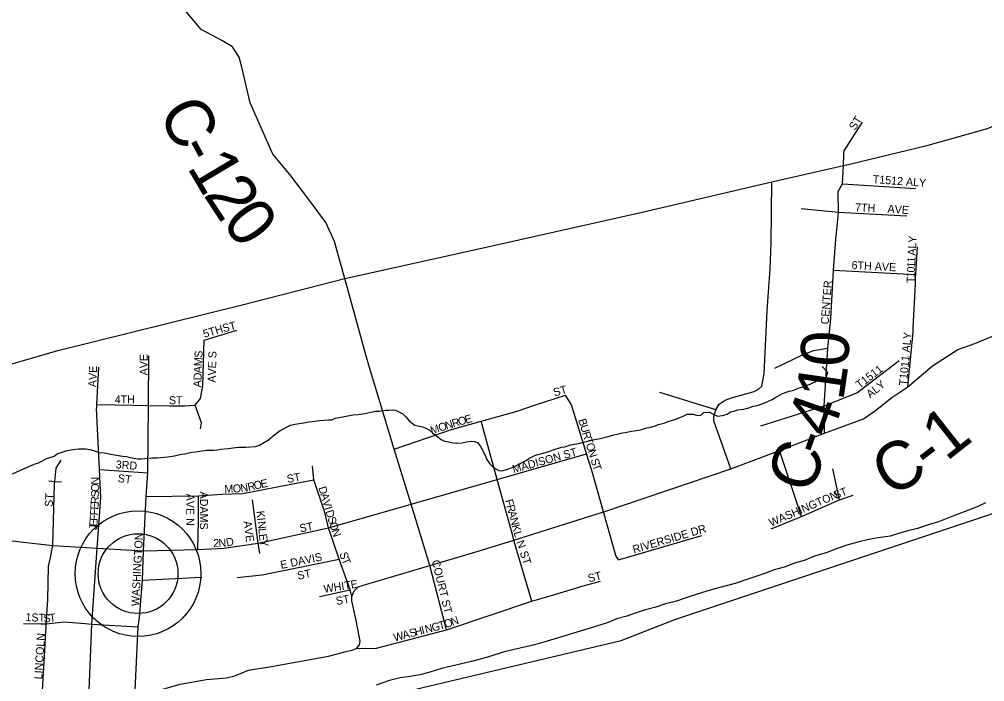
# Model space of a CAD drawing. Extents: x 1949938.81 to 1949945.61, y 152207.65 to 152214.09.
# Drawn here: x 1949943.289 to 1949944.431, y 152208.158 to 152208.942 of the extents above; entities that cross this region are included whole.
import ezdxf

# ---------------------------------------------------------------- set-up
doc = ezdxf.new("R2010")
doc.units = 0
for name, color, linetype in [('GM_X_County', 7, 'Continuous'), ('GM_X_County_Road', 7, 'Continuous'), ('GM_X_County_Road_Text', 7, 'Continuous'), ('GM_X_Major_River', 7, 'Continuous'), ('GM_X_Minor_River', 7, 'Continuous'), ('GM_X_Township', 7, 'Continuous'), ('GM_X_Township_ROW', 7, 'Continuous'), ('GM_X_Township_Subdivision', 7, 'Continuous'), ('GM_X_Township_Subdivision_Text', 7, 'Continuous'), ('GM_X_Unincorporated', 7, 'Continuous'), ('GM_X_Unincorporated_Location', 7, 'Continuous'), ('GM_X_US_Route', 7, 'Continuous')]:
    doc.layers.add(name, color=color, linetype=linetype)

msp = doc.modelspace()

# ---------------------------------------------------------------- linework, layer by layer
at = {"layer": 'GM_X_County'}
msp.add_lwpolyline([(1949942.5103, 152208.0107), (1949942.8268, 152208.0046), (1949942.9926, 152208.0073), (1949943.0418, 152208.019), (1949943.1902, 152208.0433), (1949943.3242, 152208.0581), (1949943.5551, 152208.1009), (1949944.0013, 152208.2067), (1949944.0649, 152208.2317), (1949944.5237, 152208.3846), (1949944.9116, 152208.528), (1949945.0312, 152208.5697), (1949945.2633, 152208.6645), (1949945.3744, 152208.725), (1949945.418, 152208.7524), (1949945.4377, 152208.7581), (1949945.4771, 152208.7673), (1949945.504, 152208.7825), (1949945.5586, 152208.8115), (1949945.5958, 152208.8237), (1949945.6069, 152208.8266)], dxfattribs=at)
at = {"layer": 'GM_X_County_Road'}
for points in [[(1949943.6692, 152208.6533), (1949943.6622, 152208.679), (1949943.6518, 152208.7014), (1949943.6305, 152208.7301), (1949943.6093, 152208.7583), (1949943.5891, 152208.7822), (1949943.5622, 152208.843), (1949943.5524, 152208.8851), (1949943.5493, 152208.8969), (1949943.5414, 152208.9094), (1949943.5289, 152208.9166), (1949943.5175, 152208.9227), (1949943.5043, 152208.9299), (1949943.4471, 152208.9983), (1949943.4285, 152209.0254), (1949943.4187, 152209.0361), (1949943.4074, 152209.0495), (1949943.4025, 152209.0598), (1949943.3956, 152209.0803), (1949943.3888, 152209.1174), (1949943.3776, 152209.1483), (1949943.3761, 152209.156)], [(1949944.1312, 152208.4101), (1949944.1108, 152208.4668), (1949944.1111, 152208.472), (1949944.1132, 152208.4796), (1949944.1173, 152208.4865), (1949944.1242, 152208.491), (1949944.1319, 152208.4938), (1949944.1585, 152208.5015), (1949944.1636, 152208.5041), (1949944.1677, 152208.5079), (1949944.1706, 152208.5222), (1949944.174, 152208.597), (1949944.1775, 152208.6464), (1949944.1789, 152208.6773), (1949944.1795, 152208.7497)], [(1949943.6993, 152208.5449), (1949943.6742, 152208.6353), (1949943.6692, 152208.6533)], [(1949943.6911, 152208.2011), (1949943.6916, 152208.2018), (1949943.6924, 152208.206), (1949943.6911, 152208.2119), (1949943.6877, 152208.2305), (1949943.6825, 152208.2537), (1949943.6825, 152208.2587), (1949943.6852, 152208.2656), (1949943.6901, 152208.2701), (1949943.7005, 152208.2735), (1949943.7749, 152208.2955), (1949943.8321, 152208.3124), (1949943.8743, 152208.3254), (1949943.9805, 152208.3589), (1949943.9809, 152208.359), (1949944.1312, 152208.4101), (1949944.1886, 152208.4316), (1949944.2419, 152208.4522), (1949944.2881, 152208.4691), (1949944.3024, 152208.4788), (1949944.3216, 152208.4942), (1949944.3406, 152208.507), (1949944.3696, 152208.5317), (1949944.3995, 152208.5511), (1949944.4199, 152208.5583), (1949944.4487, 152208.5701)], [(1949943.7749, 152208.2955), (1949943.7526, 152208.368), (1949943.7325, 152208.433), (1949943.7099, 152208.5088), (1949943.7036, 152208.5297), (1949943.6993, 152208.5449)], [(1949943.2833, 152208.1115), (1949943.3015, 152208.1115), (1949943.3146, 152208.1145), (1949943.3709, 152208.128), (1949943.4256, 152208.1398), (1949943.4795, 152208.155), (1949943.5105, 152208.1607), (1949943.5341, 152208.1628), (1949943.5442, 152208.1648), (1949943.5604, 152208.1715), (1949943.5851, 152208.1756), (1949943.6548, 152208.1883), (1949943.6743, 152208.1933), (1949943.684, 152208.1959), (1949943.6884, 152208.1978), (1949943.6911, 152208.2011)]]:
    msp.add_lwpolyline(points, dxfattribs=at)
at = {"layer": 'GM_X_Major_River'}
msp.add_lwpolyline([(1949944.4324, 152208.3698), (1949944.4226, 152208.3649), (1949944.4071, 152208.3592), (1949944.3927, 152208.3535), (1949944.3768, 152208.3471), (1949944.3663, 152208.3441), (1949944.3519, 152208.3395), (1949944.3405, 152208.3365), (1949944.3307, 152208.3338), (1949944.3194, 152208.3304), (1949944.3054, 152208.3282), (1949944.2944, 152208.3263), (1949944.2815, 152208.3232), (1949944.2683, 152208.3195), (1949944.2558, 152208.3153), (1949944.2452, 152208.3111), (1949944.2301, 152208.3066), (1949944.218, 152208.3013), (1949944.2074, 152208.2986), (1949944.1942, 152208.2937), (1949944.1825, 152208.2903), (1949944.1722, 152208.2865), (1949944.1617, 152208.2831), (1949944.1511, 152208.2793), (1949944.1363, 152208.2744), (1949944.1257, 152208.2713), (1949944.1121, 152208.2679), (1949944.0977, 152208.2634), (1949944.0815, 152208.2585), (1949944.0667, 152208.2535), (1949944.0539, 152208.2501), (1949944.0422, 152208.2463), (1949944.0285, 152208.2425), (1949944.0179, 152208.2391), (1949944.0081, 152208.2357), (1949943.9956, 152208.2323), (1949943.9858, 152208.2281), (1949943.9748, 152208.2244), (1949943.962, 152208.2206), (1949943.9476, 152208.2164), (1949943.9347, 152208.2122), (1949943.9215, 152208.2085), (1949943.9098, 152208.205), (1949943.8988, 152208.2016), (1949943.8886, 152208.1994), (1949943.8746, 152208.1963), (1949943.8618, 152208.1929), (1949943.8481, 152208.1888), (1949943.8376, 152208.1853), (1949943.8243, 152208.1819), (1949943.8122, 152208.1793), (1949943.8005, 152208.1766), (1949943.7888, 152208.1736), (1949943.7736, 152208.1691), (1949943.7631, 152208.166), (1949943.7517, 152208.1641), (1949943.7396, 152208.1626), (1949943.7271, 152208.1596), (1949943.7112, 152208.1539)], dxfattribs=at)
at = {"layer": 'GM_X_Minor_River'}
for points in [[(1949943.8345, 152208.437), (1949943.8367, 152208.4328), (1949943.8404, 152208.4259), (1949943.8422, 152208.4209), (1949943.8455, 152208.4163), (1949943.8496, 152208.4124), (1949943.853, 152208.4101), (1949943.8567, 152208.4081), (1949943.8601, 152208.4077), (1949943.867, 152208.4095), (1949943.875, 152208.4128), (1949943.8819, 152208.4161), (1949943.888, 152208.4194), (1949943.8922, 152208.422), (1949943.8991, 152208.4256), (1949943.9025, 152208.4267), (1949943.9075, 152208.4282), (1949943.9117, 152208.4292), (1949943.9155, 152208.4303), (1949943.9208, 152208.4325), (1949943.9307, 152208.4354), (1949943.9345, 152208.4361), (1949943.9414, 152208.4382), (1949943.9509, 152208.44), (1949943.9581, 152208.4417), (1949943.9665, 152208.4439), (1949943.9699, 152208.4446), (1949943.9763, 152208.446), (1949943.9843, 152208.4477), (1949943.9931, 152208.4502), (1949943.9965, 152208.4509), (1949944.003, 152208.4524), (1949944.0064, 152208.4531), (1949944.0132, 152208.4545), (1949944.0166, 152208.4548), (1949944.0242, 152208.4562), (1949944.0311, 152208.4583), (1949944.0345, 152208.459), (1949944.0417, 152208.4608), (1949944.0452, 152208.4623), (1949944.052, 152208.464), (1949944.0558, 152208.4655), (1949944.0619, 152208.4677), (1949944.0661, 152208.4687), (1949944.0745, 152208.4724), (1949944.0795, 152208.4746), (1949944.0859, 152208.4745), (1949944.0905, 152208.4736), (1949944.095, 152208.4732), (1949944.0985, 152208.4765), (1949944.1057, 152208.4768), (1949944.1102, 152208.4748), (1949944.1154, 152208.4721), (1949944.1211, 152208.4731), (1949944.1268, 152208.4745), (1949944.1307, 152208.4775), (1949944.1345, 152208.4782), (1949944.1394, 152208.4796), (1949944.1463, 152208.4807), (1949944.1523, 152208.4821), (1949944.1573, 152208.4839), (1949944.1626, 152208.4849), (1949944.1699, 152208.4875), (1949944.1748, 152208.4897), (1949944.1798, 152208.4919), (1949944.184, 152208.4944), (1949944.192, 152208.4989), (1949944.2, 152208.5018), (1949944.2054, 152208.5032), (1949944.2107, 152208.5054), (1949944.2164, 152208.5068), (1949944.2202, 152208.5086), (1949944.2248, 152208.5101), (1949944.2298, 152208.5123), (1949944.2344, 152208.5152), (1949944.2405, 152208.517), (1949944.2439, 152208.5185), (1949944.2459, 152208.5238), (1949944.2392, 152208.5311)], [(1949943.2809, 152208.4039), (1949943.2905, 152208.4083), (1949943.2951, 152208.4105), (1949943.3065, 152208.4153), (1949943.3118, 152208.4171), (1949943.3218, 152208.4222), (1949943.3305, 152208.4251), (1949943.334, 152208.4277), (1949943.3458, 152208.4317), (1949943.3504, 152208.4324), (1949943.3557, 152208.433), (1949943.3595, 152208.4334), (1949943.3636, 152208.4337), (1949943.3678, 152208.4336), (1949943.3727, 152208.4328), (1949943.3769, 152208.4315), (1949943.3833, 152208.4292), (1949943.3897, 152208.4287), (1949943.3972, 152208.4274), (1949943.4018, 152208.4266), (1949943.4112, 152208.4249), (1949943.4158, 152208.4244), (1949943.4222, 152208.4228), (1949943.4293, 152208.4219), (1949943.4331, 152208.4219), (1949943.446, 152208.4228), (1949943.4517, 152208.4231), (1949943.4608, 152208.4237), (1949943.465, 152208.424), (1949943.4726, 152208.4254), (1949943.4806, 152208.4271), (1949943.4851, 152208.4278), (1949943.4931, 152208.4296), (1949943.4977, 152208.4302), (1949943.5056, 152208.4312), (1949943.5106, 152208.4319), (1949943.5193, 152208.4321), (1949943.5238, 152208.4324), (1949943.5273, 152208.4331), (1949943.5364, 152208.4341), (1949943.5417, 152208.4348), (1949943.5489, 152208.4354), (1949943.5538, 152208.4357), (1949943.5572, 152208.4357), (1949943.5686, 152208.4362), (1949943.5724, 152208.4377), (1949943.5774, 152208.4403), (1949943.5839, 152208.4443), (1949943.5893, 152208.4488), (1949943.5931, 152208.4518), (1949943.5977, 152208.4551), (1949943.61, 152208.4614), (1949943.6157, 152208.4628), (1949943.6252, 152208.4645), (1949943.632, 152208.4655), (1949943.6362, 152208.4658), (1949943.6442, 152208.4672), (1949943.6548, 152208.4678), (1949943.6589, 152208.4681), (1949943.6628, 152208.4699), (1949943.67, 152208.471), (1949943.6799, 152208.4731), (1949943.6837, 152208.4738), (1949943.6901, 152208.4744), (1949943.6981, 152208.4754), (1949943.7015, 152208.4761), (1949943.7106, 152208.4782), (1949943.7152, 152208.4782), (1949943.7194, 152208.4788), (1949943.7228, 152208.4792), (1949943.7262, 152208.4795), (1949943.7307, 152208.4798), (1949943.7341, 152208.4794), (1949943.7375, 152208.4778), (1949943.7428, 152208.475), (1949943.7465, 152208.4715), (1949943.7506, 152208.4662), (1949943.7573, 152208.4615), (1949943.7622, 152208.4603), (1949943.766, 152208.4598), (1949943.7701, 152208.4582), (1949943.7739, 152208.4559), (1949943.778, 152208.4524), (1949943.7843, 152208.4477), (1949943.7884, 152208.4446), (1949943.7922, 152208.4427), (1949943.7971, 152208.4418), (1949943.8024, 152208.4406), (1949943.8062, 152208.4401), (1949943.813, 152208.4408), (1949943.8183, 152208.4418), (1949943.8244, 152208.4425), (1949943.8278, 152208.4424), (1949943.8312, 152208.4409), (1949943.8345, 152208.437)]]:
    msp.add_lwpolyline(points, dxfattribs=at)
at = {"layer": 'GM_X_Township'}
msp.add_lwpolyline([(1949942.5103, 152208.0107), (1949942.8268, 152208.0046), (1949942.9926, 152208.0073), (1949943.0418, 152208.019), (1949943.1902, 152208.0433), (1949943.3242, 152208.0581), (1949943.5551, 152208.1009), (1949944.0013, 152208.2067), (1949944.0649, 152208.2317), (1949944.5237, 152208.3846), (1949944.9116, 152208.528), (1949945.0312, 152208.5697), (1949945.2633, 152208.6645), (1949945.3744, 152208.725), (1949945.418, 152208.7524), (1949945.4377, 152208.7581), (1949945.4771, 152208.7673), (1949945.504, 152208.7825), (1949945.5586, 152208.8115), (1949945.5958, 152208.8237), (1949945.6069, 152208.8266)], dxfattribs=at)
at = {"layer": 'GM_X_Township_ROW'}
for points in [[(1949944.3468, 152208.5766), (1949944.3494, 152208.6289)], [(1949944.1132, 152208.4796), (1949944.0469, 152208.5002)]]:
    msp.add_lwpolyline(points, dxfattribs=at)
at = {"layer": 'GM_X_Township_Subdivision'}
for points in [[(1949944.2648, 152208.7825), (1949944.265, 152208.7861), (1949944.2868, 152208.8202)], [(1949944.2579, 152208.7091), (1949944.2583, 152208.7135), (1949944.2579, 152208.7381), (1949944.2631, 152208.7473), (1949944.2642, 152208.7689), (1949944.2648, 152208.7825)], [(1949944.2631, 152208.7473), (1949944.3494, 152208.7417)], [(1949944.2142, 152208.7179), (1949944.2583, 152208.7135), (1949944.3392, 152208.7094)], [(1949944.2419, 152208.4522), (1949944.2414, 152208.4844), (1949944.246, 152208.5529), (1949944.2493, 152208.5878), (1949944.2525, 152208.6449), (1949944.2554, 152208.6812), (1949944.2579, 152208.7091)], [(1949944.3494, 152208.6289), (1949944.3497, 152208.636), (1949944.3499, 152208.6398), (1949944.3518, 152208.6725)], [(1949944.2525, 152208.6449), (1949944.3499, 152208.6398)], [(1949944.3406, 152208.507), (1949944.3466, 152208.5718), (1949944.3468, 152208.5766)], [(1949943.508, 152208.5621), (1949943.5466, 152208.5742)], [(1949943.5034, 152208.4573), (1949943.5046, 152208.4642), (1949943.497, 152208.4854), (1949943.5034, 152208.493), (1949943.5061, 152208.5082), (1949943.508, 152208.5621)], [(1949943.4256, 152208.1398), (1949943.4296, 152208.2228), (1949943.4313, 152208.2339), (1949943.4347, 152208.2781), (1949943.4362, 152208.3128), (1949943.4391, 152208.3771), (1949943.4413, 152208.4052), (1949943.442, 152208.485), (1949943.4425, 152208.5435)], [(1949944.1831, 152208.5292), (1949944.2166, 152208.5453), (1949944.2291, 152208.55), (1949944.246, 152208.5529)], [(1949944.2414, 152208.4844), (1949944.2803, 152208.4999), (1949944.3303, 152208.538)], [(1949943.3807, 152208.4824), (1949943.3808, 152208.4859), (1949943.383, 152208.5303)], [(1949943.8988, 152208.4851), (1949943.9355, 152208.4972)], [(1949943.9586, 152208.4331), (1949943.9424, 152208.4856), (1949943.9355, 152208.4972)], [(1949943.3808, 152208.4859), (1949943.4244, 152208.4852)], [(1949943.4244, 152208.4852), (1949943.4245, 152208.4852), (1949943.442, 152208.485), (1949943.468, 152208.4846)], [(1949943.468, 152208.4846), (1949943.4681, 152208.4846), (1949943.4849, 152208.4843), (1949943.4906, 152208.4847), (1949943.497, 152208.4854)], [(1949943.3709, 152208.128), (1949943.375, 152208.2262), (1949943.3813, 152208.3159), (1949943.3856, 152208.3762), (1949943.3841, 152208.409), (1949943.3806, 152208.4818), (1949943.3807, 152208.4824)], [(1949943.7325, 152208.433), (1949943.8005, 152208.4565), (1949943.8355, 152208.4664), (1949943.8783, 152208.4783), (1949943.8988, 152208.4851)], [(1949944.1667, 152208.4608), (1949944.2414, 152208.4844)], [(1949943.8729, 152208.3307), (1949943.8547, 152208.3972), (1949943.8355, 152208.4664)], [(1949943.9981, 152208.3024), (1949943.9949, 152208.3073), (1949943.9805, 152208.3589), (1949943.9667, 152208.4078), (1949943.9603, 152208.4275), (1949943.9586, 152208.4331)], [(1949944.2148, 152208.3537), (1949944.1886, 152208.4316)], [(1949943.3309, 152208.3923), (1949943.331, 152208.3951), (1949943.3325, 152208.4108), (1949943.3387, 152208.4202)], [(1949943.655, 152208.34), (1949943.7526, 152208.368), (1949943.8547, 152208.3972), (1949943.9603, 152208.4275)], [(1949943.3841, 152208.409), (1949943.4413, 152208.4052)], [(1949943.6497, 152208.3615), (1949943.6496, 152208.362), (1949943.6375, 152208.3971), (1949943.6362, 152208.4134)], [(1949944.2595, 152208.3734), (1949944.2517, 152208.4099)], [(1949943.324, 152208.3956), (1949943.331, 152208.3951), (1949943.3391, 152208.3945)], [(1949943.5982, 152208.3895), (1949943.6375, 152208.3971)], [(1949943.3255, 152208.3031), (1949943.3289, 152208.3194), (1949943.3309, 152208.3923)], [(1949943.4391, 152208.3771), (1949943.5011, 152208.378), (1949943.5288, 152208.3799), (1949943.5533, 152208.3808), (1949943.5741, 152208.3848), (1949943.5982, 152208.3895)], [(1949943.5003, 152208.3144), (1949943.5011, 152208.3481), (1949943.5011, 152208.378)], [(1949943.5735, 152208.3096), (1949943.5719, 152208.322), (1949943.565, 152208.3732)], [(1949944.1786, 152208.3389), (1949944.2148, 152208.3537), (1949944.2595, 152208.3734), (1949944.2759, 152208.3786)], [(1949943.6825, 152208.2587), (1949943.6807, 152208.2667), (1949943.6674, 152208.3031), (1949943.655, 152208.34), (1949943.6497, 152208.3615)], [(1949943.0391, 152208.3366), (1949943.1443, 152208.3303), (1949943.1655, 152208.3289), (1949943.1884, 152208.326), (1949943.2008, 152208.3233), (1949943.2213, 152208.3217), (1949943.2503, 152208.322), (1949943.2669, 152208.323), (1949943.2816, 152208.3246), (1949943.294, 152208.3232), (1949943.3289, 152208.3194)], [(1949943.3289, 152208.3194), (1949943.3813, 152208.3159), (1949943.3817, 152208.3159), (1949943.4362, 152208.3128), (1949943.5003, 152208.3144), (1949943.531, 152208.3159), (1949943.5719, 152208.322), (1949943.655, 152208.34)], [(1949943.8954, 152208.2534), (1949943.8765, 152208.3171), (1949943.8743, 152208.3254), (1949943.8729, 152208.3307)], [(1949943.9981, 152208.3024), (1949944.0968, 152208.3312)], [(1949943.3209, 152208.2238), (1949943.321, 152208.2265), (1949943.3227, 152208.2549), (1949943.3237, 152208.2946), (1949943.3255, 152208.3031)], [(1949943.547, 152208.2814), (1949943.5765, 152208.2844), (1949943.6674, 152208.3031)], [(1949943.7945, 152208.2195), (1949943.7749, 152208.2955)], [(1949943.4347, 152208.2781), (1949943.5051, 152208.2818)], [(1949943.9211, 152208.261), (1949943.949, 152208.2692)], [(1949943.949, 152208.2692), (1949943.9535, 152208.2705), (1949943.977, 152208.277)], [(1949943.6444, 152208.259), (1949943.6807, 152208.2667)], [(1949943.6884, 152208.1978), (1949943.7101, 152208.1975), (1949943.7945, 152208.2195), (1949943.8954, 152208.2534), (1949943.9211, 152208.261)], [(1949943.2941, 152208.2269), (1949943.315, 152208.2265)], [(1949943.3146, 152208.1145), (1949943.319, 152208.1884), (1949943.3209, 152208.2238)], [(1949943.315, 152208.2265), (1949943.3166, 152208.2265), (1949943.321, 152208.2265), (1949943.3423, 152208.2289), (1949943.367, 152208.2268)], [(1949943.367, 152208.2268), (1949943.375, 152208.2262), (1949943.4296, 152208.2228)]]:
    msp.add_lwpolyline(points, dxfattribs=at)
at = {"layer": 'GM_X_Unincorporated'}
for radius in [0.0744, 0.0472]:
    msp.add_circle((1949943.4296, 152208.2859), radius, dxfattribs=at)
at = {"layer": 'GM_X_Unincorporated_Location'}
msp.add_line((1949943.4296, 152208.2859), (1949943.4296, 152208.2859), dxfattribs=at)
at = {"layer": 'GM_X_US_Route'}
msp.add_lwpolyline([(1949942.7677, 152208.3764), (1949942.87, 152208.4095), (1949943.1879, 152208.5073), (1949943.3347, 152208.5501), (1949943.5527, 152208.6039), (1949943.6742, 152208.6353), (1949943.838, 152208.6715), (1949944.0262, 152208.7138), (1949944.1795, 152208.7497), (1949944.2642, 152208.7689), (1949944.2681, 152208.7698), (1949944.3644, 152208.7931), (1949944.4346, 152208.8128), (1949944.628, 152208.8938), (1949944.7057, 152208.9311)], dxfattribs=at)

# ---------------------------------------------------------------- texts
at = {"layer": 'GM_X_County_Road_Text'}
for s, rotation, p in [('C', 297.4718, (1949943.4526, 152208.8317)), ('-', 298.4085, (1949943.4746, 152208.7894)), ('1', 300.6802, (1949943.4869, 152208.7668)), ('2', 303.2559, (1949943.5063, 152208.7343)), ('0', 306.8623, (1949943.5277, 152208.7018)), ('0', 86.7269, (1949944.2696, 152208.5295)), ('1', 81.6999, (1949944.264, 152208.4894)), ('4', 70.8715, (1949944.2498, 152208.445)), ('1', 38.261, (1949944.3861, 152208.418)), ('-', 70.1263, (1949944.2416, 152208.4223)), ('C', 69.9539, (1949944.2255, 152208.3783)), ('C', 29.5236, (1949944.3192, 152208.3755)), ('-', 37.6716, (1949944.3671, 152208.4034))]:
    msp.add_text(s, height=0.0568, rotation=rotation, dxfattribs=at).set_placement(p)
at = {"layer": 'GM_X_Township_Subdivision_Text'}
for s, rotation, p in [('ST', 57.2679, (1949944.278, 152208.8098)), ('T1512 ALY', 355.7947, (1949944.2987, 152208.7481)), ('7TH', 357.7094, (1949944.2779, 152208.7147)), ('AVE', 355.9142, (1949944.3162, 152208.7131)), ('Y', 86.9386, (1949944.3505, 152208.677)), ('A', 86.9167, (1949944.3497, 152208.662)), ('L', 86.9482, (1949944.3502, 152208.6703)), ('1', 86.9386, (1949944.3493, 152208.6537)), ('6TH AVE', 356.9871, (1949944.2737, 152208.6464)), ('0', 87.2512, (1949944.3487, 152208.642)), ('1', 86.9386, (1949944.349, 152208.6478)), ('T', 89.8907, (1949944.3485, 152208.6296)), ('1', 88.5636, (1949944.3485, 152208.6362)), ('CENTER', 85.7619, (1949944.2468, 152208.5806)), ('5TH', 16.9259, (1949943.5081, 152208.5647)), ('ST', 14.0342, (1949943.5307, 152208.5714)), ('T1011 ALY', 84.9571, (1949944.3394, 152208.5081)), ('AVE', 90, (1949943.441, 152208.5205)), ('S', 87.7079, (1949943.5057, 152208.5412)), ('AVE S', 88.5687, (1949943.5215, 152208.5118)), ('AVE', 88.0261, (1949943.3802, 152208.5064)), ('A', 87.7206, (1949943.5049, 152208.5229)), ('M', 87.7044, (1949943.5053, 152208.5312)), ('T1511', 37.1853, (1949944.2834, 152208.5044)), ('D', 87.7263, (1949943.5046, 152208.5145)), ('A', 88.1637, (1949943.5043, 152208.5062)), ('ST', 14.9318, (1949943.9223, 152208.4955)), ('ALY', 38.0485, (1949944.2959, 152208.4932)), ('4TH', 0, (1949943.402, 152208.4873)), ('ST', 0, (1949943.4661, 152208.4864)), ('E', 16.1989, (1949943.8177, 152208.4632)), ('M', 18.4074, (1949943.7772, 152208.4505)), ('O', 18.4085, (1949943.7867, 152208.4537)), ('N', 17.6207, (1949943.7946, 152208.4563)), ('R', 16.3071, (1949943.8025, 152208.4588)), ('O', 16.1846, (1949943.8097, 152208.4609)), ('B', 287.3098, (1949943.9503, 152208.4677)), ('U', 287.3109, (1949943.9526, 152208.4605)), ('R', 287.2858, (1949943.955, 152208.4525)), ('T', 287.3319, (1949943.9573, 152208.4454)), ('O', 287.3094, (1949943.9593, 152208.439)), ('MADISON ST', 15.6687, (1949943.874, 152208.4047)), ('N', 287.2881, (1949943.9617, 152208.4311)), ('3RD', 355.6015, (1949943.4029, 152208.4106)), ('S', 287.3104, (1949943.965, 152208.4207)), ('T', 289.1392, (1949943.967, 152208.414)), ('ST', 10.618, (1949943.6066, 152208.3931)), ('N', 89.9956, (1949943.3835, 152208.3912)), ('ST', 352.8746, (1949943.4052, 152208.3944)), ('R', 12.158, (1949943.5602, 152208.3837)), ('O', 12.1988, (1949943.5675, 152208.3853)), ('E', 12.1956, (1949943.5757, 152208.3871)), ('S', 89.115, (1949943.3834, 152208.376)), ('O', 89.9519, (1949943.3835, 152208.3828)), ('ADAMS', 270, (1949943.5029, 152208.383)), ('M', 2.3344, (1949943.5319, 152208.3814)), ('O', 2.4915, (1949943.5419, 152208.3818)), ('N', 9.0396, (1949943.5514, 152208.3823)), ('D', 286.6247, (1949943.6428, 152208.3876)), ('WASHINGTON', 23.2784, (1949944.1787, 152208.3413)), ('ST', 20.556, (1949944.2546, 152208.3738)), ('ST', 86.4256, (1949943.3285, 152208.3647)), ('R', 86.8391, (1949943.383, 152208.3681)), ('AVE N', 270, (1949943.4866, 152208.3805)), ('A', 286.6245, (1949943.6452, 152208.3797)), ('V', 286.6245, (1949943.6476, 152208.3717)), ('F', 285.0339, (1949943.8637, 152208.3726)), ('F', 86.3638, (1949943.3821, 152208.3547)), ('E', 86.3614, (1949943.3825, 152208.3614)), ('K', 276.3734, (1949943.5696, 152208.3598)), ('I', 286.6243, (1949943.65, 152208.3637)), ('D', 286.6245, (1949943.6512, 152208.3597)), ('R', 285.0098, (1949943.8654, 152208.3662)), ('E', 86.3639, (1949943.3813, 152208.3414)), ('F', 86.3804, (1949943.3817, 152208.3481)), ('I', 276.3517, (1949943.5705, 152208.3516)), ('S', 286.6242, (1949943.6536, 152208.3517)), ('A', 285.0241, (1949943.8673, 152208.3589)), ('N', 285.0342, (1949943.8695, 152208.3509)), ('J', 86.3694, (1949943.381, 152208.3373)), ('AVE', 277.8491, (1949943.5543, 152208.3477)), ('N', 276.3863, (1949943.5709, 152208.3474)), ('L', 276.3515, (1949943.5719, 152208.3391)), ('ST', 10.6201, (1949943.6216, 152208.3347)), ('O', 287.7885, (1949943.6555, 152208.3451)), ('N', 289.5585, (1949943.6582, 152208.3369)), ('K', 285.0124, (1949943.8717, 152208.3428)), ('RIVERSIDE DR', 16.5259, (1949944.0164, 152208.3097)), ('WASHINGTON', 86.9862, (1949943.431, 152208.2472)), ('2', 0.3064, (1949943.5186, 152208.3173)), ('N', 3.8584, (1949943.5251, 152208.3173)), ('D', 11.0954, (1949943.5347, 152208.318)), ('E', 276.3954, (1949943.5726, 152208.3325)), ('Y', 280.4362, (1949943.5735, 152208.3252)), ('L', 285.3839, (1949943.8739, 152208.3347)), ('I', 288.1465, (1949943.8758, 152208.3278)), ('N', 290.6836, (1949943.8772, 152208.3234)), ('E DAVIS', 11.7248, (1949943.5991, 152208.2914)), ('S', 285.9693, (1949943.6679, 152208.31)), ('T', 292.947, (1949943.6701, 152208.3024)), ('ST', 288.4255, (1949943.8811, 152208.311)), ('ST', 11.3105, (1949943.619, 152208.2787)), ('COURT ST', 283.8277, (1949943.777, 152208.3009)), ('ST', 14.0374, (1949943.9632, 152208.2755)), ('WHITE', 8.8423, (1949943.65, 152208.2631)), ('ST', 10.6205, (1949943.6646, 152208.2487)), ('1ST', 357.5102, (1949943.2962, 152208.2298)), ('S', 4.2059, (1949943.318, 152208.2281)), ('T', 6.864, (1949943.3251, 152208.2286)), ('N', 19.2841, (1949943.8015, 152208.224)), ('H', 14.6041, (1949943.7582, 152208.212)), ('I', 14.6047, (1949943.7662, 152208.2141)), ('N', 14.6011, (1949943.7703, 152208.2152)), ('G', 14.5993, (1949943.7783, 152208.2173)), ('T', 15.1893, (1949943.7865, 152208.2194)), ('O', 18.2886, (1949943.7935, 152208.2213)), ('LINCOLN', 86.2468, (1949943.316, 152208.1606)), ('W', 14.6061, (1949943.7332, 152208.2055)), ('A', 14.6118, (1949943.7437, 152208.2083)), ('S', 14.612, (1949943.7517, 152208.2104))]:
    msp.add_text(s, height=0.00947, rotation=rotation, dxfattribs=at).set_placement(p)

doc.saveas('drawing.dxf')
